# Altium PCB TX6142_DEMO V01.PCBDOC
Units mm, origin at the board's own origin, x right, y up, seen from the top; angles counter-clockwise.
Board outline 152.4 x 101.6 mm, 2 copper layers (Top Layer, Bottom Layer); 15 components, 1 nets, 51 pads, 21 vias.
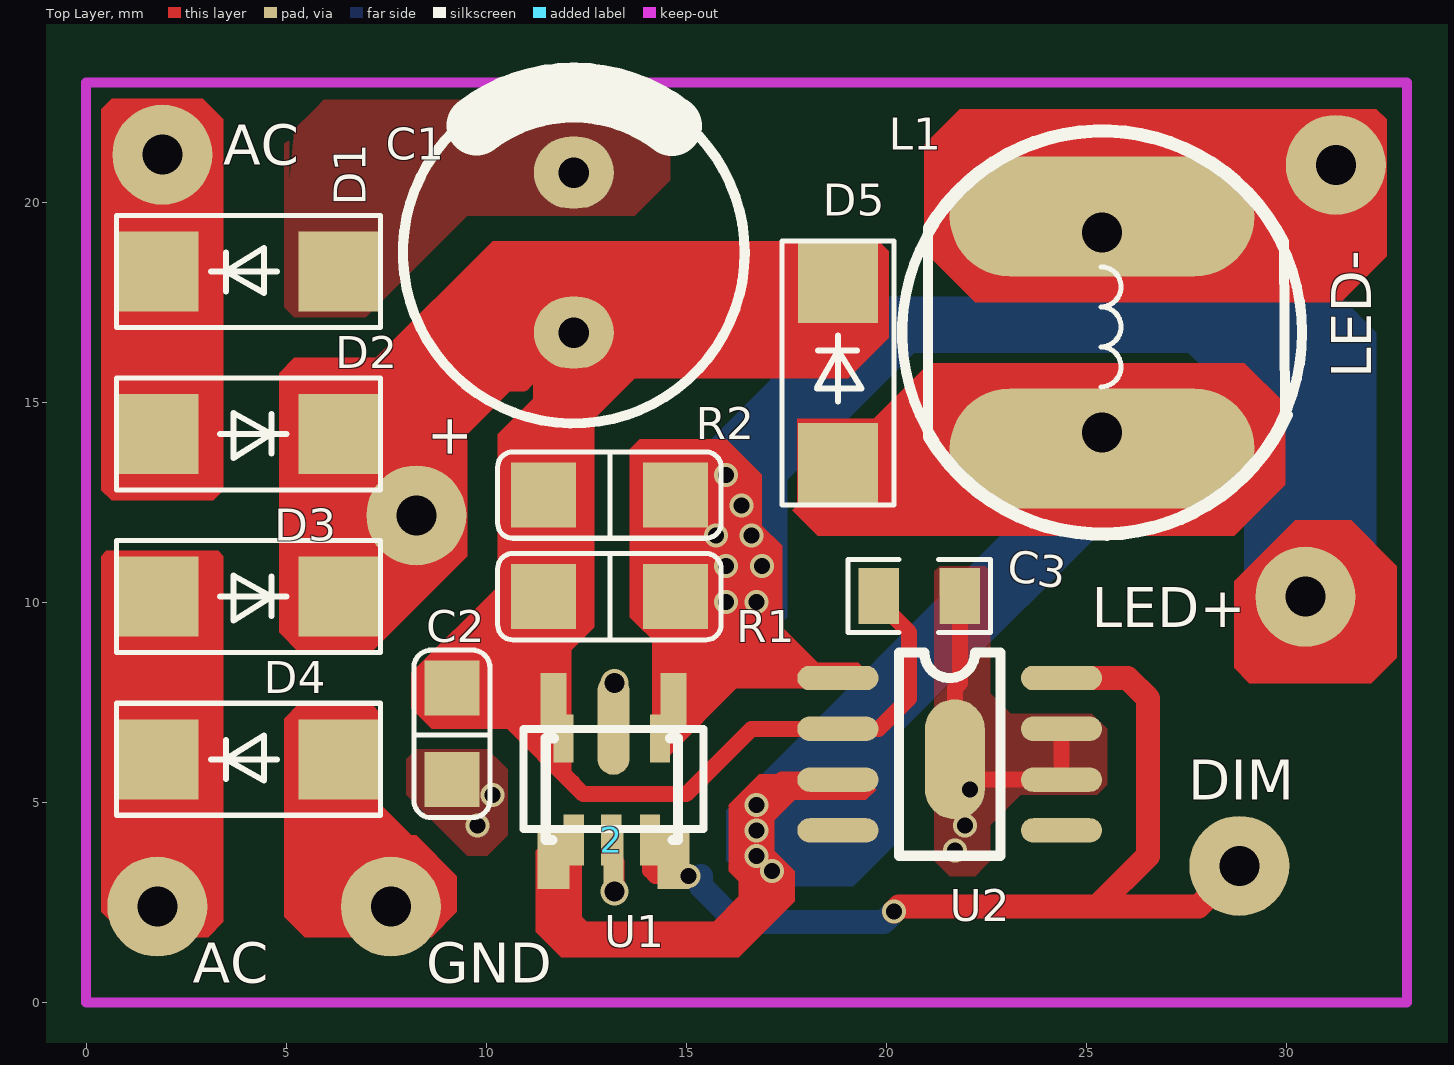
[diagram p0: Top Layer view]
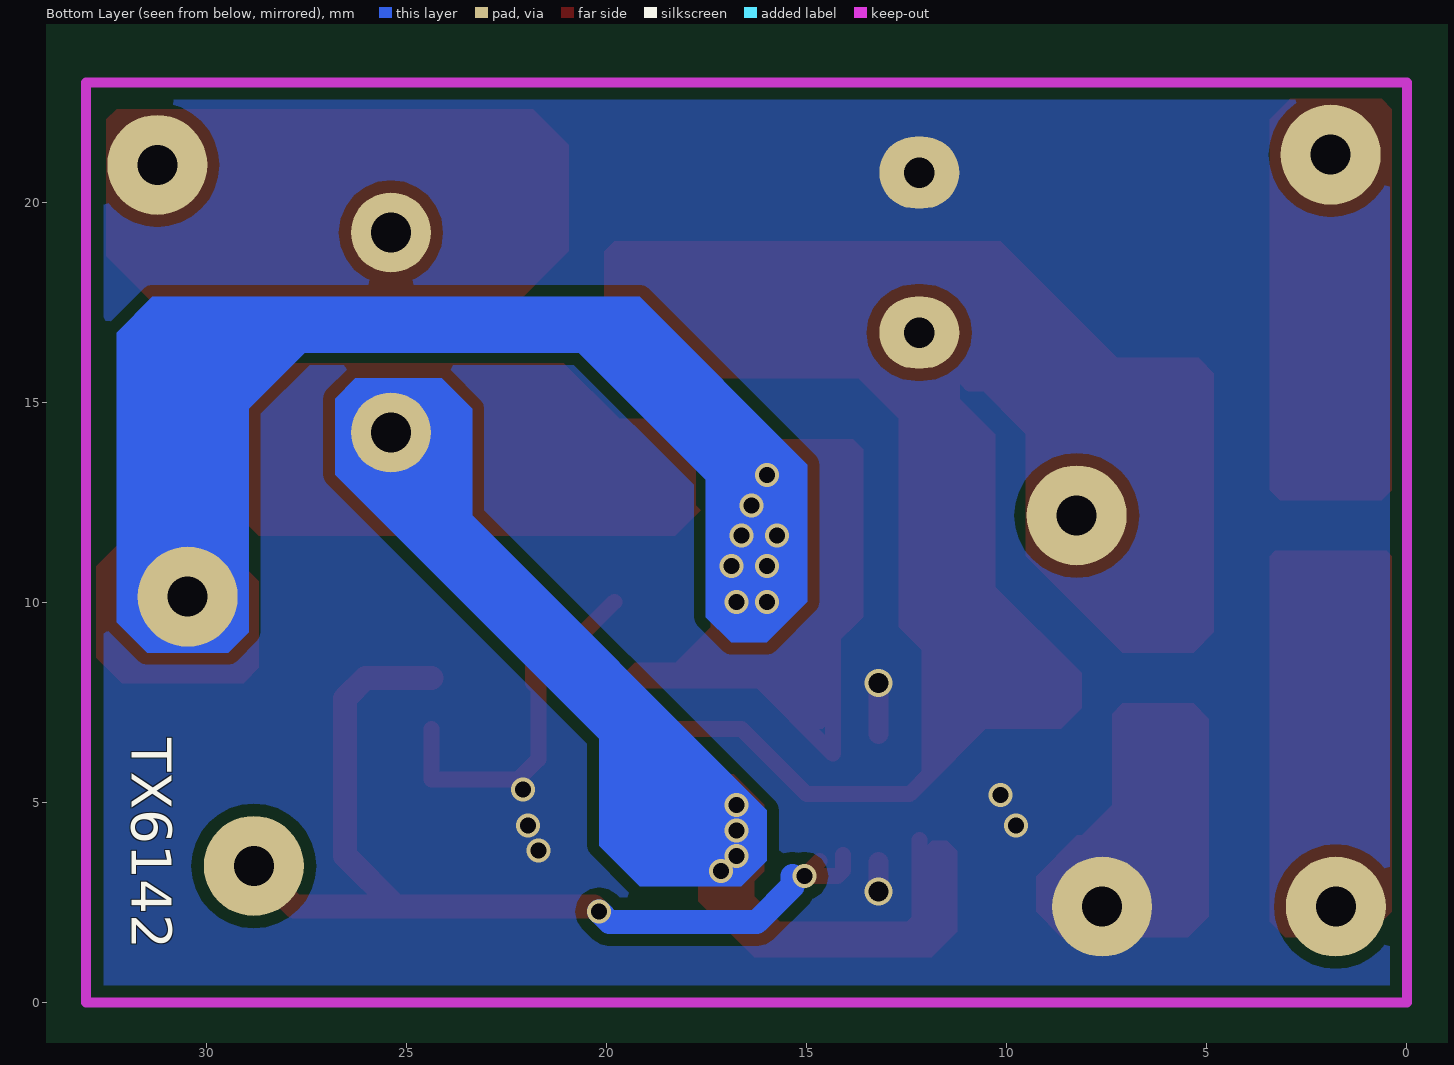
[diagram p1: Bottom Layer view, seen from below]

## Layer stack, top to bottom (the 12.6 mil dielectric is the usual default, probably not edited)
Top Layer: signal copper 0.0356
Dielectric: dielectric 0.32, FR-4, Dk 4.8
Bottom Layer: signal copper 0.0356

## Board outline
-50.8,-42.18 101.6,-42.18 101.6,59.42 -50.8,59.42

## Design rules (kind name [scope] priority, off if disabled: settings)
Clearance [All] p1: gap=0.3
ComponentClearance [All] p1 off: gap=0.254 collisioncheckmode=3 verticalgap=0.254 showdistances=FALSE
FabricationTestPointUsage TestPointUsage [All] p1: valid=0 allowmultiple=FALSE
FabricationTestpoint Testpoint [All] p1: side=3 testpointundercomponent=TRUE minsize=1.016 maxsize=2.54 preferedsize=1.524 minholesize=0 maxholesize=1.016 preferedholesize=0.813 testpointgrid=0.025 allowsidetop=TRUE allowsidebottom=TRUE usegrid=TRUE gridtolerance=0
Height [All] p1 off: minheight=0 maxheight=25.4 prefheight=12.7
PolygonConnect [All] p1: connectstyle=Direct reliefconductorwidth=0.254 reliefentries=4 polygonreliefangle="90 Angle"
RoutingVias [All] p1: holewidth=0.711 width=1.27 viastyle="Through Hole" minholewidth=0.711 minwidth=1.27 maxholewidth=0.711 maxwidth=1.27
SilkscreenOverComponentPads [All] p1: minsilkscreentomaskgap=0.254
SolderMaskExpansion [All] p1: expansion=0.102
Width [All] p1: maxlimit=2 minlimit=0.4 preferedwidth=0.5
23 further rules are at their usual default settings.

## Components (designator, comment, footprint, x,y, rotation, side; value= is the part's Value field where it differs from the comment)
2 "TX6142" SOT-23-5 14.097,6.604 r180 top
C1 "Comment" C8*12 12.192,16.748 r0 top
C2 "Comment" R0805 9.144,5.572 r0 top
C3 "Comment" C0805T 20.828,10.16 r0 top
D1 "Comment" SMA 4.064,18.272 r0 top
D2 "Comment" SMA 4.064,14.208 r180 top
D3 "Comment" SMA 4.064,10.144 r180 top
D4 "Comment" SMA 4.064,6.08 r0 top
D5 "Comment" SMA 18.796,15.732 r270 top
L1 "Comment" CD105 25.4,16.748 r0 top
R1 "Comment" R1206 14.732,10.144 r270 top
R2 "Comment" R1206 14.732,12.684 r270 top
U1 "Comment" SOT89-5 11.684,3.54 r0 top
U2 "Comment" SO-8 18.796,8.112 r0 top
? "Comment" L9*12 25.4,16.748 r90 top

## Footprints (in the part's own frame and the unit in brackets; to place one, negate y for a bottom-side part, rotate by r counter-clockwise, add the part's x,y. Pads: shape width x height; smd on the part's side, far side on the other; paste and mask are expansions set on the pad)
C8*12 [mm]
  oval 2x1.8 hole 0.762: 1(0,0) 2(0,4)
  silkscreen extent -4.27,-2.27 4.27,6.27
C0805T [mil]
  rect 40x55 smd: 1(40,0) 2(-40,0)
  silkscreen extent -70,-36 70,36
CD105 [mm]
  oval 7.62x3 smd: 1(0,-2.9) 2(0,2.9)
  silkscreen extent -4.36,-5.08 4.64,5.08
L9*12 [mm]
  round 2 hole 1: 1(-2.5,0) 2(2.5,0)
  silkscreen extent -5,-5 5,5
R0805 [mil]
  rect 54x54 smd: 1(0,0) 2(0,90)
  silkscreen extent -38,-38 38,128
R1206 [mil]
  rect 64x64 smd: 1(0,0) 2(0,-130)
  silkscreen extent -42,-175 43,45
SMA [mm]
  rect 2x2 smd: 1(2.25,0) 2(-2.25,0)
  silkscreen extent -3.3,-1.4 3.3,1.4
SO-8 [mil]
  oval 80x24 smd: 1(0,0) 2(0,-50) 3(0,-100) 4(0,-150) 5(220,-150) 6(220,-100) 7(220,-50) 8(220,0)
  silkscreen extent 60,-175 160,25
SOT89-5 [mm]
  rect 0.8x1.4 smd: 1(0,0) 3(3,0)
  rect 0.5x1.4 smd: 2(1.5,0)
  oval 0.8x2.5 smd: 2(1.5,3.4)
  rect 0.65x1.4 smd: 4(3,4) 5(0,4)
  silkscreen extent -0.75,0.8 3.75,3.3
SOT-23-5 [mil]
  rect 20x50 smd: 13(38,100) 14(0,100) 15(75,100)
  silkscreen extent -28,0 103,100

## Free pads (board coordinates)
  rect 0.5x1.2 smd: 0(11.938,6.604) 0(14.351,6.604)
  oval 1.5x3 smd: 0(21.717,6.08)
  round 2.5 hole 1: 1(31.242,20.939) 2(30.48,10.144) 3(1.778,2.397) 4(1.905,21.193) 5(8.255,12.176) 6(7.62,2.397) 7(28.829,3.413)

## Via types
v1: diameter 0.6, hole 0.4, Top Layer to Bottom Layer, 19 vias
v2: diameter 0.7, hole 0.5, Top Layer to Bottom Layer, 2 vias

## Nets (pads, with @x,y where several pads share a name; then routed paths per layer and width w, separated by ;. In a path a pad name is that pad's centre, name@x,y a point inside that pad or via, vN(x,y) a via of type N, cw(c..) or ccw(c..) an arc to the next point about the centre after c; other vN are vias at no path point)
GND: 2.13 C1.2 C2.1 C3.1 D1.1 pad.0@21.717,6.08 pad.6 U1.2 U2.6 U2.7 | length 8.9
  Top Layer w0.4: U1.2@13.184,3.54 U1.2@13.208,3.516 ; C3.1@21.844,10.017 21.844,7.985 21.717,7.858 21.717,6.08 22.225,5.572 U2.6 U2.7
  Top Layer w0.5: v2(13.208,2.778) U1.2@13.208,3.516
  other v1: 21.717,3.794 9.779,4.429 21.971,4.429 10.16,5.191 22.098,5.318
  other v2: 13.208,7.985
pads on no net: 2.14 2.15 ?.1 ?.2 C1.1 C2.2 C3.2 D1.2 D2.1 D2.2 D3.1 D3.2 D4.1 D4.2 D5.1 D5.2 L1.1 L1.2 R1.1 R1.2 R2.1 R2.2 U1.1 U1.3 U1.4 U1.5 U2.1 U2.2 U2.3 U2.4 U2.5 U2.8
copper on no net: | length 123.9
  Top Layer w0.4: 6.314,10.144 6.35,10.18 6.35,14.462 ; 6.35,14.081 7.747,15.478 10.922,15.478 12.192,16.748 12.192,13.192 11.303,12.303 11.303,7.921 11.684,7.54 9.97,7.54 9.652,7.858 ; 6.477,5.953 6.858,5.572 ; 11.43,6.731 11.176,6.985 10.668,6.985 12.154,5.499 12.154,5.483 ; 11.43,7.54 11.43,6.207 ; 11.684,3.54 11.684,2.143 12.065,1.762 15.748,1.762 16.764,2.778 v1(16.764,4.937) 17.399,5.572 18.796,5.572 ; 11.747,6.159 11.747,7.16 11.43,6.842 11.43,6.207 ; 11.938,9.271 11.938,5.699 12.43,5.207 ; 12.192,1.889 12.192,4.064 ; 12.446,16.748 13.68,17.982 18.796,17.982 ; 14.097,3.683 14.097,3.302 14.24,3.159 v1(15.065,3.159) 14.684,3.54 ; 14.351,9.398 14.351,6.223 16.24,8.112 16.256,8.112 ; 14.684,7.54 15.256,8.112 18.796,8.112 ; 14.732,7.588 14.732,12.684 ; 19.177,13.446 19.939,12.684 26.162,12.684 ; 19.812,10.017 20.574,9.255 20.574,7.604 19.812,6.842 18.796,6.842 16.637,6.842 15.002,5.207 12.43,5.207 ; 25.908,18.526 27.178,18.526 29.591,20.939 31.242,20.939 ; 11.43,6.207 12.43,5.207
  Top Layer w0.5: 13.208,6.715 13.208,7.985
  Top Layer w0.6: v1(20.193,2.27) 20.32,2.397 25.273,2.397 ; 24.384,8.112 26.035,8.112 26.543,7.604 26.543,3.667 25.273,2.397 ; 28.829,3.413 27.813,2.397 25.273,2.397
  Bottom Layer w0.4: 29.972,10.017 30.48,10.525
  Bottom Layer w0.6: 15.367,3.159 15.367,2.905 16.256,2.016 19.939,2.016 v1(20.193,2.27)
  other v1: 17.145,3.286 16.764,3.667 16.764,4.302 16.002,10.017 16.764,10.017 16.002,10.906 16.891,10.906 15.748,11.668 16.637,11.668 16.383,12.43 16.002,13.192

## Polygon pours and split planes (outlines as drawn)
GND on Top Layer "TopOverlay-No Net" (solid, remove dead copper, pour order 1000): 5.08,20.431 5.08,21.701 5.715,22.336 5.969,22.59 10.668,22.59 13.462,22.59 14.605,21.447 14.605,20.558 13.716,19.669 10.287,19.669 9.525,19.669 7.874,18.018 6.985,17.129 5.461,17.129 5.207,17.129 4.953,17.383 4.953,21.574 5.207,21.828
GND on Top Layer "TopOverlay-No Net" (solid, remove dead copper, pour order 1001): 8.255,6.334 10.033,6.334 10.414,5.953 10.541,5.826 10.541,4.302 10.541,4.175 10.033,3.667 9.525,3.667 9.017,4.175 8.001,5.191 8.001,5.826 8.001,6.08 8.255,6.334
GND on Top Layer "TopOverlay-No Net" (solid, remove dead copper, pour order 1002): 24.765,7.223 23.114,7.223 22.606,7.731 22.606,10.779 22.479,10.906 21.717,10.906 21.336,10.906 21.209,10.779 21.209,3.54 21.59,3.159 22.225,3.159 22.479,3.413 22.606,3.54 22.606,4.429 23.368,5.191 23.749,5.191 25.273,5.191 25.527,5.445 25.527,6.842 25.146,7.223 24.765,7.223
GND on Bottom Layer "TopOverlay-No Net" (solid, remove dead copper, pour order 1003): 0,23 0,0.254 0.254,0 32.877,0 33.02,-0.143 33.02,22.619 32.639,23 0,23

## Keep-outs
Keep-Out Layer:
  lines w0.254: 0,0 0,23 33.02,23 33.02,0 0,0

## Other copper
Top Layer:
  region: 0.508,11.287 0.381,11.16 0.381,2.27 1.016,1.635 3.048,1.635 3.429,2.016 3.429,11.16 3.302,11.287
  region: 0.381,22.336 0.381,12.811 0.635,12.557 3.175,12.557 3.429,12.811 3.429,22.082 2.921,22.59 0.635,22.59
  region: 4.953,7.096 4.953,2.143 5.461,1.635 8.636,1.635 9.271,2.27 9.271,3.159 8.255,4.175 8.128,4.175 7.366,4.937 7.366,7.223 7.112,7.477 5.334,7.477
  region: 5.207,16.113 7.239,16.113 10.16,19.034 19.812,19.034 20.066,18.78 20.066,16.621 19.05,15.605 13.716,15.605 12.7,14.589 12.7,9.382 12.065,8.747 12.065,7.477 11.43,6.842 8.636,6.842 8.128,7.35 8.128,8.239 10.287,10.398 10.287,14.208 11.176,15.097 11.176,15.478 10.795,15.478 9.525,14.208 9.525,11.16 7.112,8.747 5.334,8.747 4.826,9.255 4.826,15.732
  region: 13.843,14.081 13.589,13.827 13.589,9.636 14.351,8.874 14.351,7.096 14.605,6.842 14.859,6.842 15.875,7.858 19.431,7.858 19.685,8.112 19.304,8.493 18.288,8.493 17.399,9.382 17.399,11.414 16.891,11.922 16.891,13.192 16.002,14.081
  region: 17.78,14.589 19.685,14.589 21.082,15.986 28.956,15.986 29.972,14.97 29.972,12.938 28.702,11.668 18.288,11.668 17.653,12.303 17.78,12.43
  region: 21.844,22.336 32.258,22.336 32.512,22.082 32.512,18.653 31.369,17.51 22.225,17.51 20.955,18.78 20.955,21.447
  region: 30.226,12.049 28.702,10.525 28.702,8.366 29.083,7.985 32.131,7.985 32.766,8.62 32.766,10.906 31.623,12.049
  region: 19.367,5.699 16.828,5.699 16.066,4.937 16.066,3.286 16.319,3.032 16.319,2.651 15.684,2.016 12.509,2.016 12.128,2.397 12.128,3.794 11.874,4.048 11.493,4.048 11.239,3.794 11.239,1.762 11.874,1.127 16.319,1.127 17.716,2.524 17.716,3.286 17.209,3.794 17.209,4.556 17.716,5.064 19.494,5.064 19.748,5.318
Bottom Layer:
  region: 16.002,4.81 16.002,3.54 16.637,2.905 19.177,2.905 20.193,3.921 20.193,6.588 26.797,13.192 26.797,15.097 26.289,15.605 24.13,15.605 23.368,14.843 23.368,12.176
  region: 14.986,13.446 19.177,17.637 31.369,17.637 32.258,16.748 32.258,9.509 31.496,8.747 29.464,8.747 28.956,9.255 28.956,14.843 27.559,16.24 20.701,16.24 17.526,13.065 17.526,9.636 16.891,9.001 16.002,9.001 14.986,10.017

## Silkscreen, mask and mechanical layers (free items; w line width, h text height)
Top Overlay:
  text "AC" at 3.429,20.939 h1
  text "LED-" at 32.131,15.605 h1 r90
  text "+" at 9.525,13.573 h1 r90
  text "LED+" at 25.146,9.382 h1
  text "DIM" at 27.559,5.064 h1
  text "AC" at 2.667,0.492 h1
  text "GND" at 8.509,0.492 h1
Bottom Overlay:
  text "TX6142" at 31.877,6.604 h1 r90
